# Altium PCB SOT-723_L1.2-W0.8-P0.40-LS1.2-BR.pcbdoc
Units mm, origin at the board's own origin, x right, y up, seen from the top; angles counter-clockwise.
Board outline 14.46 x 14.05 mm, 2 copper layers (Top Layer, Bottom Layer), stack 0 mm thick; 1 components, 0 nets, 3 pads, 0 vias.
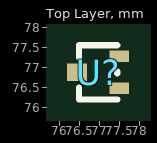
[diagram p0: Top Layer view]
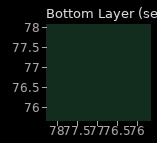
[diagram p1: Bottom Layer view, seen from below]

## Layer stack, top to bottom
Top Layer: signal copper (thickness not stored)
Bottom Layer: signal copper (thickness not stored)

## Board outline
84.313,69.85 69.85,69.85 69.85,83.902 84.313,83.902

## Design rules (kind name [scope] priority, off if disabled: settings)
PasteMaskExpansion "Paste Mask Expansion" [All] p1: expansion=0
SolderMaskExpansion "Solder Mask Expansion" [IsVia] p1: expansion=-25.4 istentingtop=TRUE
SolderMaskExpansion "Solder Mask Expansion" [All] p2: expansion=0.051 istentingtop=FALSE

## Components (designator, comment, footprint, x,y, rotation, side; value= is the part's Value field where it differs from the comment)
U? "" SOT-723_L1.2-W0.8-P0.40-LS1.2-BR 76.974,76.876 r0 top

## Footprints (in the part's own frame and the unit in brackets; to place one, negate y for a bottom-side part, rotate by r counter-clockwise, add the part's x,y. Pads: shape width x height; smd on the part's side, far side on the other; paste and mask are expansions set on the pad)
SOT-723_L1.2-W0.8-P0.40-LS1.2-BR [mm]
  rect 0.489x0.294 smd: 1(0.53,-0.4) 2(0.53,0.4)
  rect 0.489x0.434 smd: 3(-0.53,0)
  silkscreen extent -0.48,-0.68 0.48,0.68

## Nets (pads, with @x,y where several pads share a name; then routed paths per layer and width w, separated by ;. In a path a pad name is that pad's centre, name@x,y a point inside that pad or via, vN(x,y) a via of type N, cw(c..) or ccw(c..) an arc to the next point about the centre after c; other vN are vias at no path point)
pads on no net: U?.1 U?.2 U?.3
